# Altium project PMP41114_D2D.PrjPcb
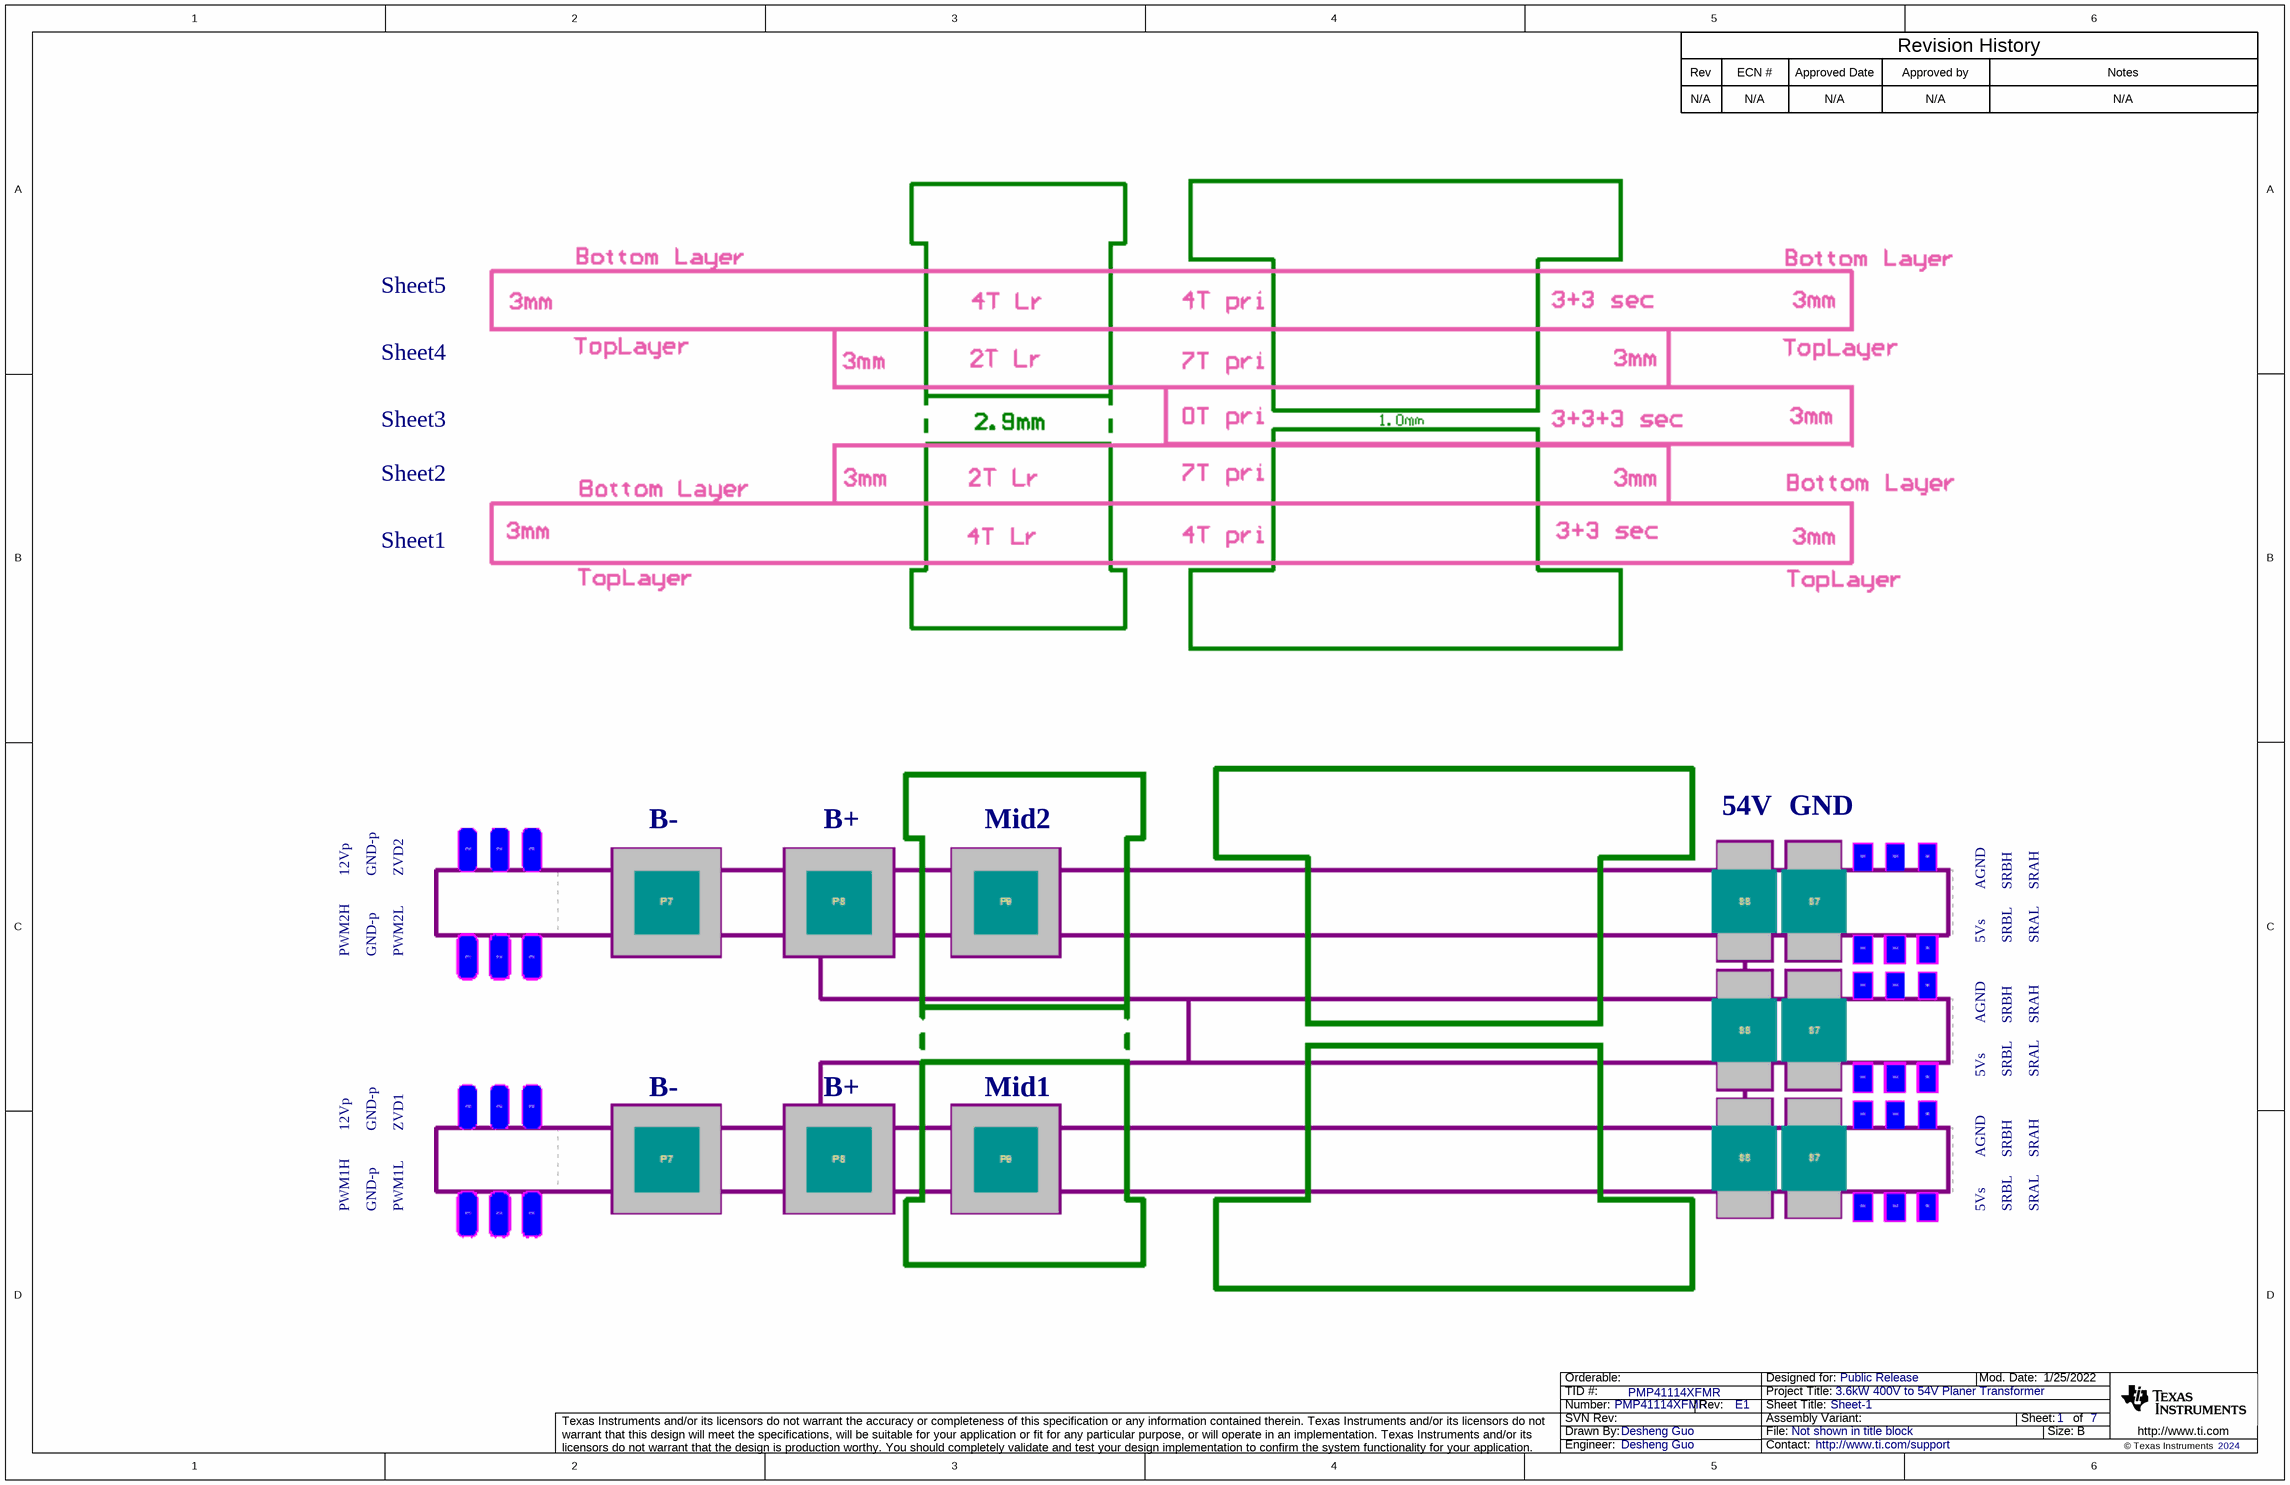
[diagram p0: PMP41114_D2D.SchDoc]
CopyrightYear: 2024; PCB_Layout: Desheng Guo; PCB_Rev: E1; PRJ_Customer: Public Release; PRJ_Engineer: Desheng Guo; PRJ_Number: PMP41114XFMR; PRJ_Title: 3.6kW 400V to 54V Planer Transformer; SCH_Rev: E1; TechSupport: http://www.ti.com/support; TID: PMP41114XFMR
7 sheets, 148 parts. Net scope: flat (ports and power ports of the same name join across sheets).
Board file: PMP41114_XFMR.PcbDoc
Sheets:
  PMP41114_D2D.SchDoc
  PMP41114_D2D_Sheet1.SchDoc
  PMP41114_D2D_Sheet2.SchDoc
  PMP41114_D2D_Sheet3.SchDoc
  PMP41114_D2D_Sheet5.SchDoc
  PMP41114_D2D_Sheet4.SchDoc
  PMP41114_D2D_Hardware.SchDoc

## Sheet PMP41114_D2D.SchDoc: Sheet-1
size 431 x 279 mm; Date: Not shown in title block; ApprovedBy: Not shown in title block; CheckedBy: Not shown in title block; Author: Not shown in title block; CompanyName: Not shown in title block; DrawnBy: Desheng Guo; Engineer: Not shown in title block; Organization: Not shown in title block; Address1: Not shown in title block; Address2: Not shown in title block; Address3: Not shown in title block; Address4: Not shown in title block; DocumentNumber: 1; Revision: Use project parameter SCH_Rev; SheetNumber: 1; SheetTotal: 7; PageSetup: Record=PageOptions¦CenterHorizontal=True¦CenterVertical=True¦PrintScale=1.00¦XCorrection=1.00¦YCorrection=1.00¦PrintKind=0¦BorderSize=5000000¦LeftOffset=0¦BottomOffset=0¦Orientation=2¦PaperLength=1000¦PaperWidth=1000¦Scale=100¦PaperSource=15¦PrintQuality=600¦MediaType=1¦DitherType=10¦PaperKind=Letter¦PrintScaleMode=1

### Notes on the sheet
- Rev
- N/A
- ECN #
- Approved Date
- Approved by
- Revision History
- Notes
- Sheet5
- Sheet4
- Sheet3
- Sheet2
- Sheet1
- B-
- B+
- Mid2
- 54V
- GND
- 12Vp
- GND-p
- ZVD2
- AGND
- SRBH
- SRAH
- PWM2H
- PWM2L
- 5Vs
- SRBL
- SRAL
- Mid1
- ZVD1
- PWM1H
- PWM1L

## Sheet PMP41114_D2D_Sheet1.SchDoc
size 431 x 279 mm; Date: Not shown in title block; ApprovedBy: Not shown in title block; CheckedBy: Not shown in title block; Author: Not shown in title block; CompanyName: Not shown in title block; Engineer: Not shown in title block; Organization: Not shown in title block; Address1: Not shown in title block; Address2: Not shown in title block; Address3: Not shown in title block; Address4: Not shown in title block; DocumentNumber: 2; Revision: Use project parameter SCH_Rev; SheetNumber: 2; SheetTotal: 7; PageSetup: Record=PageOptions¦CenterHorizontal=True¦CenterVertical=True¦PrintScale=1.00¦XCorrection=1.00¦YCorrection=1.00¦PrintKind=0¦BorderSize=5000000¦LeftOffset=0¦BottomOffset=0¦Orientation=2¦PaperLength=1000¦PaperWidth=1000¦Scale=100¦PaperSource=15¦PrintQuality=600¦MediaType=1¦DitherType=10¦PaperKind=Letter¦PrintScaleMode=1
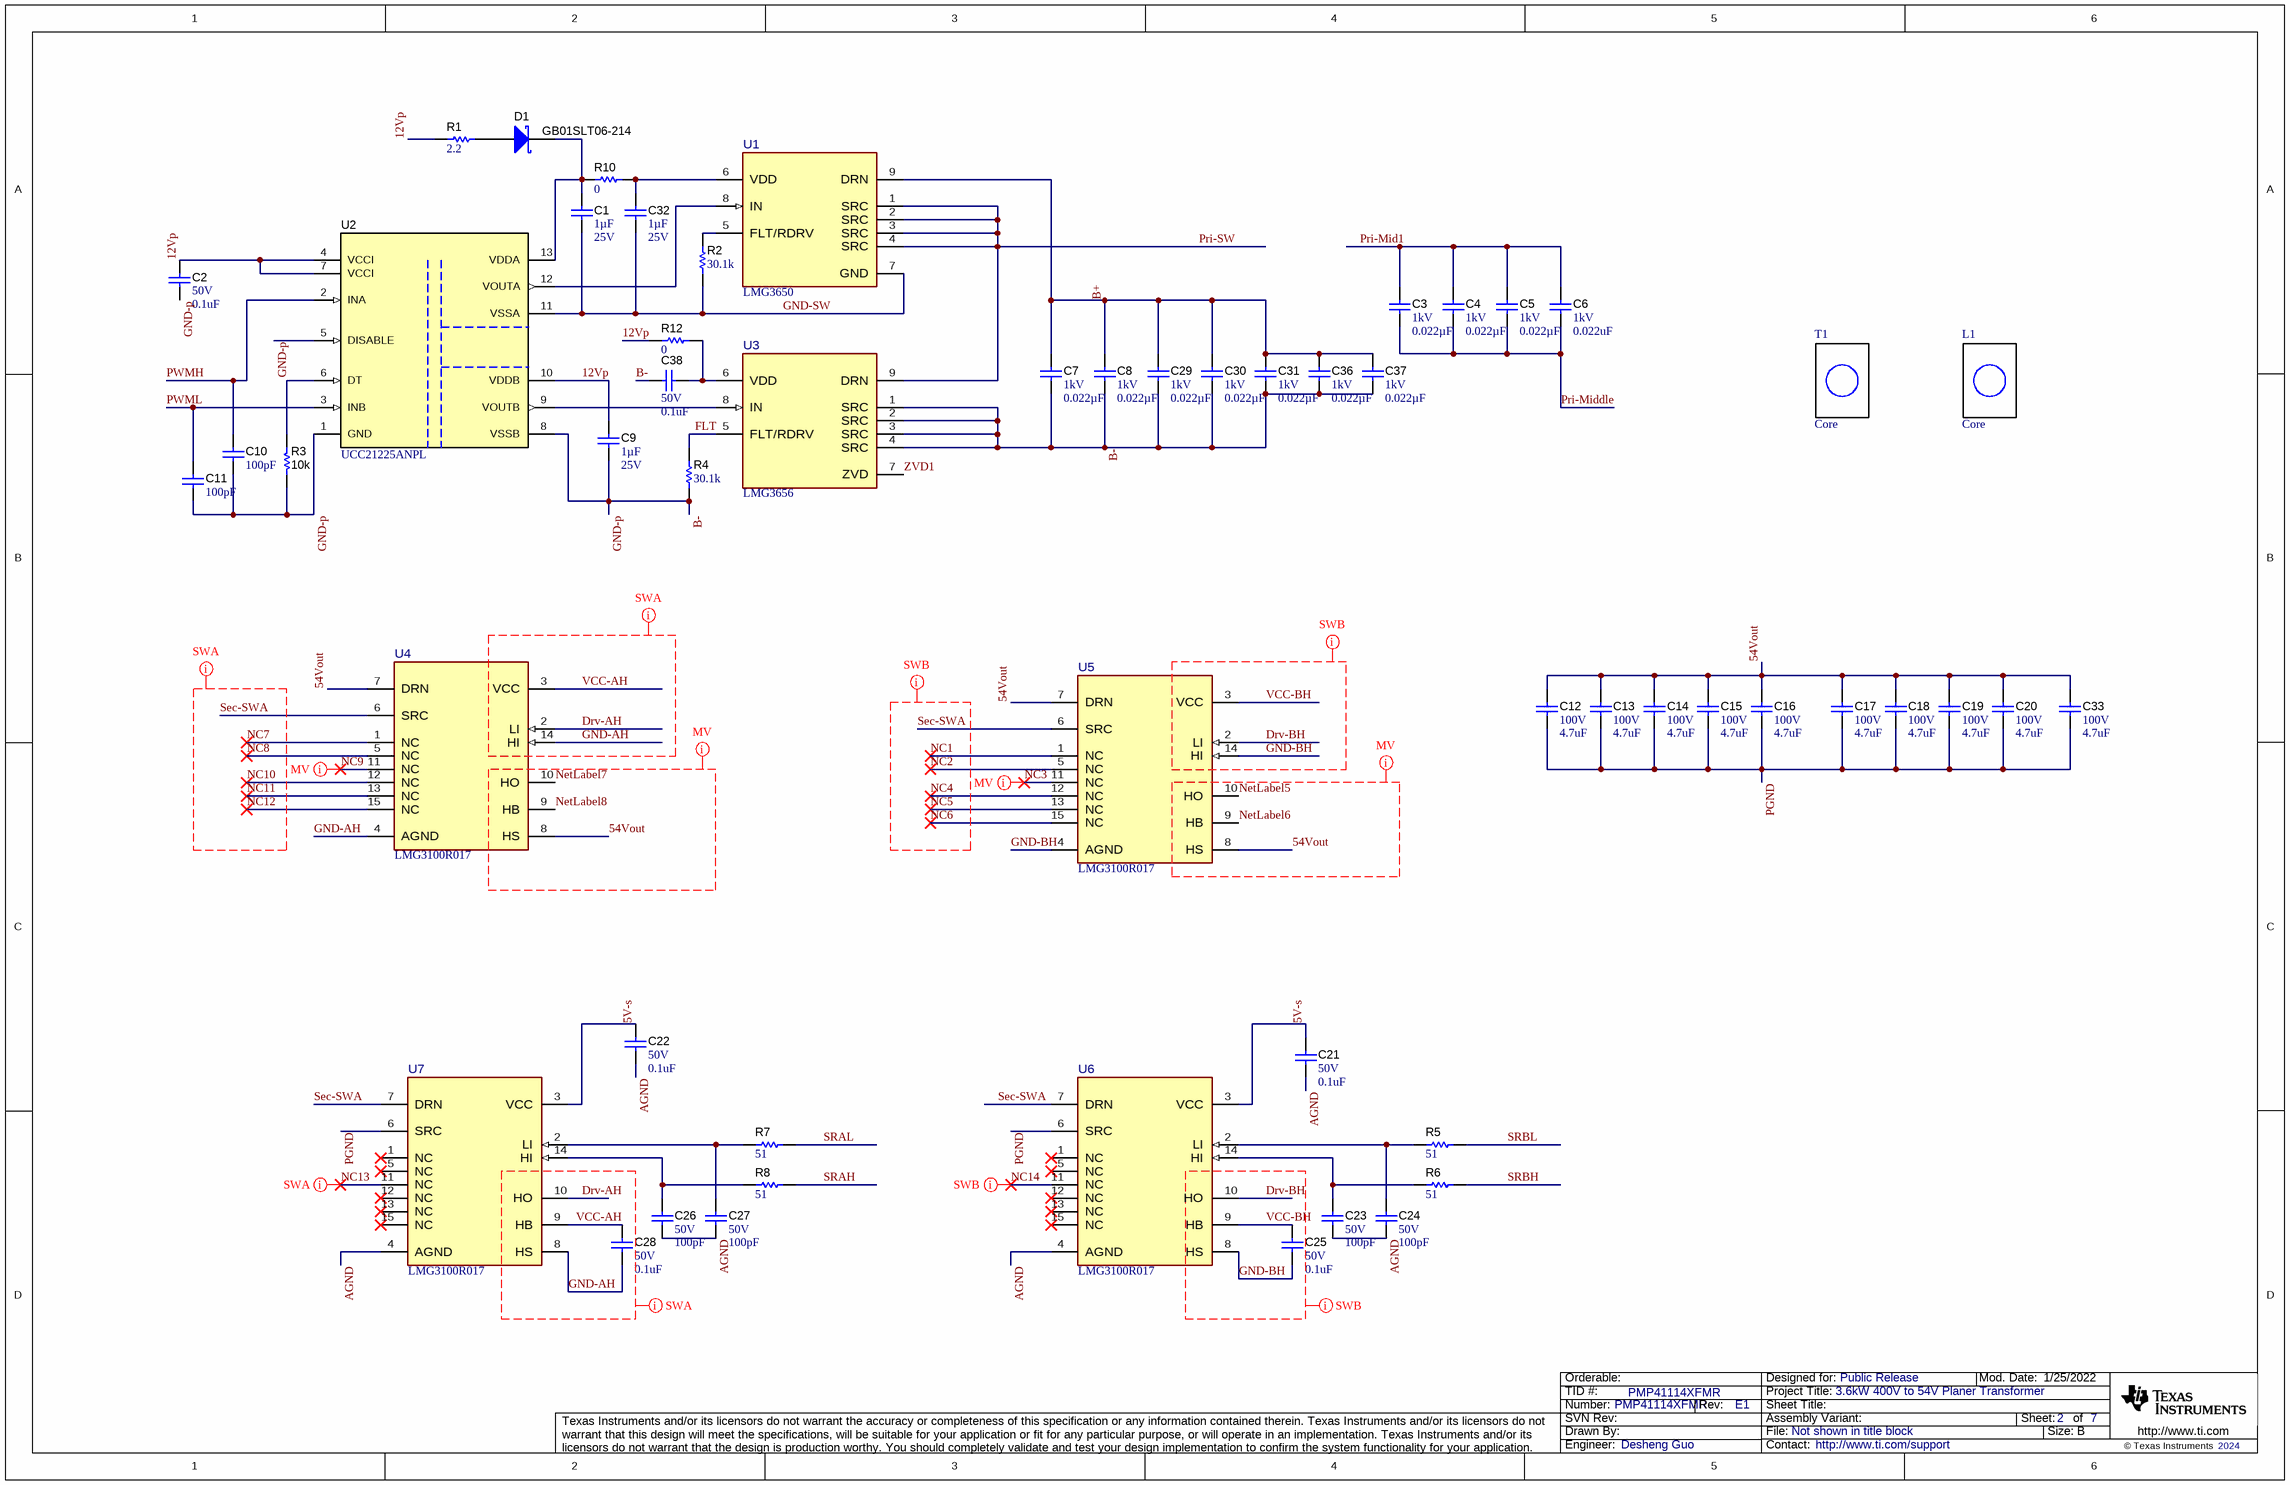
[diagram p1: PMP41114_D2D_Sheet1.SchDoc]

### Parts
C1  Cap_F: 1µF  VDC_V: 25V  [0603]  (hidden comment: CGJ3E1X7R1E105K080AC)
C2  VDC_V: 50V  ValueDisplayed: 0.1uF  [0402]  (hidden comment: C1005X7R1H104K050BB)
C3  VDC_V: 1kV  ValueDisplayed: 0.022µF  [1206_190]  (hidden comment: C1206C223KDRACTU)
C4  VDC_V: 1kV  ValueDisplayed: 0.022µF  [1206_190]  (hidden comment: C1206C223KDRACTU)
C5  VDC_V: 1kV  ValueDisplayed: 0.022µF  [1206_190]  (hidden comment: C1206C223KDRACTU)
C6  VDC_V: 1kV  ValueDisplayed: 0.022uF  [1206_190]  (hidden comment: C1206C223KDRACTU)
C7  VDC_V: 1kV  ValueDisplayed: 0.022µF  [1206_190]  (hidden comment: C1206C223KDRACTU)
C8  VDC_V: 1kV  ValueDisplayed: 0.022µF  [1206_190]  (hidden comment: C1206C223KDRACTU)
C9  Cap_F: 1µF  VDC_V: 25V  [0603]  (hidden comment: CGJ3E1X7R1E105K080AC)
C10  ValueDisplayed: 100pF  [0402]  (hidden comment: 885012205055)
C11  ValueDisplayed: 100pF  [0402]  (hidden comment: 885012205055)
C12  VDC_V: 100V  ValueDisplayed: 4.7uF  [1206_180]  (hidden comment: GRM31CZ72A475KE11L)
C13  VDC_V: 100V  ValueDisplayed: 4.7uF  [1206_180]  (hidden comment: GRM31CZ72A475KE11L)
C14  VDC_V: 100V  ValueDisplayed: 4.7uF  [1206_180]  (hidden comment: GRM31CZ72A475KE11L)
C15  VDC_V: 100V  ValueDisplayed: 4.7uF  [1206_180]  (hidden comment: GRM31CZ72A475KE11L)
C16  VDC_V: 100V  ValueDisplayed: 4.7uF  [1206_180]  (hidden comment: GRM31CZ72A475KE11L)
C17  VDC_V: 100V  ValueDisplayed: 4.7uF  [1206_180]  (hidden comment: GRM31CZ72A475KE11L)
C18  VDC_V: 100V  ValueDisplayed: 4.7uF  [1206_180]  (hidden comment: GRM31CZ72A475KE11L)
C19  VDC_V: 100V  ValueDisplayed: 4.7uF  [1206_180]  (hidden comment: GRM31CZ72A475KE11L)
C20  VDC_V: 100V  ValueDisplayed: 4.7uF  [1206_180]  (hidden comment: GRM31CZ72A475KE11L)
C21  VDC_V: 50V  ValueDisplayed: 0.1uF  [0402]  (hidden comment: GRM155R71H104ME14D)
C22  VDC_V: 50V  ValueDisplayed: 0.1uF  [0402]  (hidden comment: GRM155R71H104ME14D)
C23  VDC_V: 50V  ValueDisplayed: 100pF  [0402]  (hidden comment: CC0402KRX7R9BB101)
C24  VDC_V: 50V  ValueDisplayed: 100pF  [0402]  (hidden comment: CC0402KRX7R9BB101)
C25  VDC_V: 50V  ValueDisplayed: 0.1uF  [0402]  (hidden comment: C1005X7R1H104K050BE)
C26  VDC_V: 50V  ValueDisplayed: 100pF  [0402]  (hidden comment: CC0402KRX7R9BB101)
C27  VDC_V: 50V  ValueDisplayed: 100pF  [0402]  (hidden comment: CC0402KRX7R9BB101)
C28  VDC_V: 50V  ValueDisplayed: 0.1uF  [0402]  (hidden comment: C1005X7R1H104K050BE)
C29  VDC_V: 1kV  ValueDisplayed: 0.022µF  [1206_190]  (hidden comment: C1206C223KDRACTU)
C30  VDC_V: 1kV  ValueDisplayed: 0.022µF  [1206_190]  (hidden comment: C1206C223KDRACTU)
C31  VDC_V: 1kV  ValueDisplayed: 0.022µF  [1206_190]  (hidden comment: C1206C223KDRACTU)
C32  Cap_F: 1µF  VDC_V: 25V  [0603]  (hidden comment: CGJ3E1X7R1E105K080AC)
C33  VDC_V: 100V  ValueDisplayed: 4.7uF  [1206_180]  (hidden comment: GRM31CZ72A475KE11L)
C36  VDC_V: 1kV  ValueDisplayed: 0.022µF  [1206_190]  (hidden comment: C1206C223KDRACTU)
C37  VDC_V: 1kV  ValueDisplayed: 0.022µF  [1206_190]  (hidden comment: C1206C223KDRACTU)
C38  VDC_V: 50V  ValueDisplayed: 0.1uF  [0402]  (hidden comment: C1005X7R1H104K050BB)
D1  GB01SLT06-214  [SMB]
L1  Core  [ER25/10/11]  (no BOM)
R1  ValueDisplayed: 2.2  [0805_HV]  (hidden comment: RC0805JR-072R2L)
R2  ValueDisplayed: 30.1k  [0402]  (hidden comment: CRCW040230K1FKED)
R3  ValueDisplayed: 10k  [0402]  (hidden comment: CRCW040210K0JNED)
R4  ValueDisplayed: 30.1k  [0402]  (hidden comment: CRCW040230K1FKED)
R5  ValueDisplayed: 51  [0402]  (hidden comment: RC0402JR-0751RL)
R6  ValueDisplayed: 51  [0402]  (hidden comment: RC0402JR-0751RL)
R7  ValueDisplayed: 51  [0402]  (hidden comment: RC0402JR-0751RL)
R8  ValueDisplayed: 51  [0402]  (hidden comment: RC0402JR-0751RL)
R10  ValueDisplayed: 0  [0402]  (hidden comment: RC0402JR-070RL)
R12  ValueDisplayed: 0  [0402]  (hidden comment: RC0402JR-070RL)
T1  Core  [PQ32]  (no BOM)
U1  PartNumber: LMG3650  [KLA0009A-MFG]  (hidden comment: LMG365x)
U2  UCC21225ANPL  [NPL0013A]
U3  PartNumber: LMG3656  [KLA0009A-MFG]  (hidden comment: LMG365x)
U4  LMG3100R017  [VBE0015A-MFG]
U5  LMG3100R017  [VBE0015A-MFG]
U6  LMG3100R017  [VBE0015A-MFG]
U7  LMG3100R017  [VBE0015A-MFG]

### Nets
5V-s: C21.1 C22.1 U6.3(VCC) U7.3(VCC)  [project net 5V-s_2]
12Vp: C2.1 C9.1 R1.1 R12.1 U2.4(VCCI) U2.7(VCCI) U2.10(VDDB)  [project net 12Vp_2]
54Vout: C12.1 C13.1 C14.1 C15.1 C16.1 C17.1 C18.1 C19.1 C20.1 C33.1 U4.7(DRN) U4.8(HS) U5.7(DRN) U5.8(HS)  [project net 54Vout_2]
AGND: C21.2 C22.2 C23.2 C24.2 C26.2 C27.2 U6.4(AGND) U7.4(AGND)  [project net AGND_2]
B+: C7.1 C8.1 C29.1 C30.1 C31.1 C36.1 C37.1 U1.9(DRN)  [project net B+_2]
B-: C2.2 C7.2 C8.2 C9.2 C10.2 C11.2 C29.2 C30.2 C31.2 C36.2 C37.2 C38.1 R3.1 R4.1 U2.1(GND) U2.5(DISABLE) U2.8(VSSB) U3.1(SRC) U3.2(SRC) U3.3(SRC) U3.4(SRC)  [also labelled GND-p]  [project net B-_2]
Drv-AH: U4.2(LI) U7.10(HO)  [project net Drv-AH_2]
Drv-BH: U5.2(LI) U6.10(HO)  [project net Drv-BH_2]
FLT: R4.2 U3.5(FLT/RDRV)  [project net FLT_2]
GND-AH: C28.2 U4.4(AGND) U4.14(HI) U7.8(HS)  [project net GND-AH_2]
GND-BH: C25.2 U5.4(AGND) U5.14(HI) U6.8(HS)  [project net GND-BH_2]
GND-SW: C1.2 C32.2 R2.1 U1.7(GND) U2.11(VSSA)  [project net GND-SW_2]
NC1: U5.1(NC)  [project net NC1_2]
NC2: U5.5(NC)  [project net NC2_2]
NC3: U5.11(NC)  [project net NC3_2]
NC4: U5.12(NC)  [project net NC4_2]
NC5: U5.13(NC)  [project net NC5_2]
NC6: U5.15(NC)  [project net NC6_2]
NC7: U4.1(NC)  [project net NC7_2]
NC8: U4.5(NC)  [project net NC8_2]
NC9: U4.11(NC)  [project net NC9_2]
NC10: U4.12(NC)  [project net NC10_2]
NC11: U4.13(NC)  [project net NC11_2]
NC12: U4.15(NC)  [project net NC12_2]
NC13: U7.11(NC)  [project net NC13_2]
NC14: U6.11(NC)  [project net NC14_2]
NetLabel5: U5.10(HO)  [project net NetLabel5_2]
NetLabel6: U5.9(HB)  [project net NetLabel6_2]
NetLabel7: U4.10(HO)  [project net NetLabel7_2]
NetLabel8: U4.9(HB)  [project net NetLabel8_2]
PGND: C12.2 C13.2 C14.2 C15.2 C16.2 C17.2 C18.2 C19.2 C20.2 C33.2 U6.6(SRC) U7.6(SRC)  [project net PGND_2]
Pri-Mid1: C3.1 C4.1 C5.1 C6.1  [project net Pri-Mid1_2]
Pri-Middle: C3.2 C4.2 C5.2 C6.2  [project net Pri-Middle_2]
Pri-SW: U1.1(SRC) U1.2(SRC) U1.3(SRC) U1.4(SRC) U3.9(DRN)  [project net Pri-SW_2]
PWMH: C10.1 U2.2(INA)  [project net PWMH_2]
PWML: C11.1 U2.3(INB)  [project net PWML_2]
Sec-SWA: U4.6(SRC) U5.6(SRC) U6.7(DRN) U7.7(DRN)  [project net Sec-SWA_2]
SRAH: R8.2  [project net SRAH_2]
SRAL: R7.2  [project net SRAL_2]
SRBH: R6.2  [project net SRBH_2]
SRBL: R5.2  [project net SRBL_2]
VCC-AH: C28.1 U4.3(VCC) U7.9(HB)  [project net VCC-AH_2]
VCC-BH: C25.1 U5.3(VCC) U6.9(HB)  [project net VCC-BH_2]
ZVD1: U3.7(ZVD)  [project net ZVD1_2]
NetC1_1: C1.1 D1.1(K) R10.1 U2.13(VDDA)
NetC23_1: C23.1 R6.1 U6.14(HI)
NetC24_1: C24.1 R5.1 U6.2(LI)
NetC26_1: C26.1 R8.1 U7.14(HI)
NetC27_1: C27.1 R7.1 U7.2(LI)
NetC32_1: C32.1 R10.2 U1.6(VDD)
NetC38_2: C38.2 R12.2 U3.6(VDD)
NetD1_2: D1.2(A) R1.2
NetR2_2: R2.2 U1.5(FLT/RDRV)
NetR3_2: R3.2 U2.6(DT)
NetU1_8: U1.8(IN) U2.12(VOUTA)
NetU2_9: U2.9(VOUTB) U3.8(IN)

Not connected (* = marked no-connect by the designer): U6 1(NC)* 5(NC)* 12(NC)* 13(NC)* 15(NC)*; U7 1(NC)* 5(NC)* 12(NC)* 13(NC)* 15(NC)*

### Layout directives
net class SWA: Drv-AH, GND-AH, NC7, NC8, NC10, NC11, NC12, NC13_2, Sec-SWA, VCC-AH
net class SWB: Drv-BH, GND-BH, NC1, NC2, NC4, NC5, NC6, NC14_2, Sec-SWA, VCC-BH
net class MV: 54Vout, NC3_2, NC9_2, NetLabel5, NetLabel6, NetLabel7, NetLabel8

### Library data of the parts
C1 C9 C32 = CMP-0083856-1: CAP, CERM, 1 µF, 25 V,+/- 10%, X7R, 0603; Manufacturer: TDK; TaMin_C: -55°C; Polarized: N; SizeAreaWB_mm2: 4.68; U/M: EA; Value: 1uF; TaMax_C: 125°C; SizeZ_mm: 1; SizeX_mm: 1.6; SizeY_mm: 0.8; SizeArea_mm2: 1.28; AEC Category: Q200
C2 C38 = CMP-0006297-2: CAP, CERM, 0.1 uF, 50 V, +/- 10%, X7R, 0402; Manufacturer: TDK; TaMin_C: -55°C; ESR_ohm: 0.039064; Polarized: N; SizeAreaWB_mm2: 3; Value1: 0.039064 ohm; U/M: EA; Value: 0.1uF; TaMax_C: 125°C; SizeZ_mm: 0.6; SizeX_mm: 1; SizeY_mm: 0.5; Cap_F: 100nF; IRMS_A: 8.14669dA; AEC Category: Q200
C3-C8 C29-C31 C36 C37 = CMP-0084048-1: CAP, CERM, 0.022 µF, 1000 V,+/- 10%, X7R, AEC-Q200 Grade 1, 1206; Manufacturer: Kemet; TaMin_C: -55°C; Polarized: N; SizeAreaWB_mm2: 10.92; U/M: EA; Value: 0.022uF; TaMax_C: 125°C; SizeZ_mm: 1.9; SizeX_mm: 3.2; SizeY_mm: 1.6; Cap_Case: 1206; Value2: 1000V; SizeArea_mm2: 5.12; AEC Qualified: Y; Cap_F: 22nF; AEC Grade: 1; AEC Category: Q200
C10 C11 = CMP-0006230-2: CAP, CERM, 100 pF, 50 V, +/- 10%, X7R, 0402; Manufacturer: Wurth Elektronik; Polarized: N; Value: 100pF; U/M: EA; Value1: Unknown; VDC_V: 50V; TaMin_C: -55°C; TaMax_C: 125°C; AEC Category: Q200; SizeArea_mm2: 0.5; SizeAreaWB_mm2: 3; SizeX_mm: 1; SizeZ_mm: 0.6
C12-C20 C33 = CMP-0008802-2: CAP, CERM, 4.7 uF, 100 V, +/- 10%, X7R, 1206; Manufacturer: Samsung; TaMin_C: -55°C; Polarized: N; SizeAreaWB_mm2: 10.92; Value1: Unknown; U/M: EA; Value: 4.7uF; TaMax_C: 125°C; SizeZ_mm: 1.8; SizeX_mm: 3.2; SizeY_mm: 1.6; Cap_Case: 1206; SizeArea_mm2: 5.12; Cap_F: 4.7µF; AEC Category: Q200
C21 C22 = CMP-0006675-2: CAP, CERM, 0.1 uF, 50 V, +/- 20%, X7R, 0402; Manufacturer: MuRata; TaMin_C: -55°C; Polarized: N; SizeAreaWB_mm2: 3; Value1: Unknown; U/M: EA; Value: 0.1uF; TaMax_C: 125°C; SizeZ_mm: 0.6; SizeX_mm: 1; SizeY_mm: 0.5; Cap_F: 100nF; AEC Category: Q200
C23 C24 C26 C27 = CMP-0006305-2: CAP, CERM, 100 pF, 50 V, +/- 10%, X7R, 0402; Manufacturer: Yageo America; TaMin_C: -55°C; Polarized: N; SizeAreaWB_mm2: 3; Value1: Unknown; U/M: EA; Value: 100pF; TaMax_C: 125°C; SizeZ_mm: 0.6; SizeX_mm: 1; SizeY_mm: 0.5; AEC Category: Q200
C25 C28 = CMP-0064946-2: CAP, CERM, 0.1 uF, 50 V,+/- 10%, X7R, 0402; Manufacturer: TDK; TaMin_C: -55°C; Polarized: N; SizeAreaWB_mm2: 3; Value1: Unknown; U/M: EA; Value: 0.1uF; TaMax_C: 125°C; SizeZ_mm: 0.6; SizeX_mm: 1; SizeY_mm: 0.5; Cap_F: 100nF; AEC Category: Q200
D1 = CMP-0076998-2: Diode, Schottky, 650 V, 1 A, SMB; Manufacturer: GeneSiC Semiconductor; Value1: 1A; SizeZ_mm: 2.6; Value: 650V; SizeAreaWB_mm2: 44.156; TJmax_C: 175°C; RJC_CperW: 3.55; SizeArea_mm2: 21.336; AEC Category: Q101; Value2: 2V; SizeY_mm: 3.81; SizeX_mm: 5.6
L1 T1 = CorePlace
R1 = CMP-0020812-2: RES, 2.2, 5%, 0.125 W, 0805; Manufacturer: Yageo America; Power_W: 125mW; TempCo: 200 ppm/C; Value_Code: 2R20; U/M: EA; Value: 2.2; EIA_Code: E24; SizeX_mm: 2; SizeY_mm: 1.25; SizeZ_mm: 1.45; Value2: 0.125W; SizeArea_mm2: 2.5; VDC_V: 150V; AEC Category: Q200
R2 R4 = CMP-0026284-2: RES, 30.1 k, 1%, 0.063 W, AEC-Q200 Grade 0, 0402; Manufacturer: Vishay-Dale; Power_W: 63mW; TempCo: 100 ppm/C; Value_Code: 30k1; Value: 30.1k; EIA_Code: E96; SizeX_mm: 1; SizeY_mm: 0.5; SizeZ_mm: 0.6; Value2: 0.063W; AEC Qualified: Y; VDC_V: 50V; AEC Category: Q200; AEC Grade: 0
R3 = CMP-0026825-5: RES, 10 k, 5%, 0.063 W, AEC-Q200 Grade 0, 0402; Manufacturer: Vishay-Dale; Value: 10k; Value_Code: 10k0; Power_W: 63mW; Value2: 0.063W; VDC_V: 50V; TempCo: 200 ppm/C; EIA_Code: E24; AEC Category: Q200; AEC Qualified: Y; AEC Grade: 0; SizeArea_mm2: 0.5; SizeX_mm: 1; SizeZ_mm: 0.6
R5-R8 = CMP-0027006-2: RES, 51, 5%, 0.0625 W, 0402; Manufacturer: Yageo America; Power_W: 62.5mW; TempCo: 100 ppm/C; Value_Code: 51R0; U/M: EA; Value: 51; EIA_Code: E24; SizeX_mm: 1; SizeY_mm: 0.5; SizeZ_mm: 0.6; AEC Qualified: N; VDC_V: 50V; AEC Category: Q200
R10 R12 = CMP-0027004-2: RES, 0, 5%, 0.063 W, 0402; Manufacturer: Yageo America; Power_W: 63mW; TempCo: 200 ppm/C; Value_Code: 0000; U/M: EA; Value: 0; EIA_Code: E24; SizeX_mm: 1; SizeY_mm: 0.5; SizeZ_mm: 0.6; Value2: 0.063W; VDC_V: 50V; AEC Category: Q200
U1 U3 = CMP-0120607-2: Manufacturer: Texas Instruments; SizeZ_mm: 2.35mm; AEC Qualified: No; Standoff Height: 0.1mm; AEC Category: Q200; CompType: IC
U2 = CMP-0013548-2: 4A/6A Isolated Dual-Channel Gate Driver, NPL0013A (VLGA-13); Manufacturer: Texas Instruments; SizeX_mm: 5; CompType: IC; SizeZ_mm: 1; SizeArea_mm2: 25; SizeAreaWB_mm2: 49; U/M: EA
U4-U7 = CMP-0043784-1: 100-V, 64-A GaN with Integrated Driver; Manufacturer: Texas Instruments; SizeZ_mm: 0.85mm; AEC Qualified: No; Max Supply Voltage: 5.25V; Min Supply Voltage: 4.75V; Nominal Supply Current: 3mA; Number Of Drivers: 1; Propagation Delay: 55ns; Standoff Height: 0mm; TJmax_C: +125°C

## Sheet PMP41114_D2D_Sheet2.SchDoc
size 431 x 279 mm; Date: Not shown in title block; ApprovedBy: Not shown in title block; CheckedBy: Not shown in title block; Author: Not shown in title block; CompanyName: Not shown in title block; Engineer: Not shown in title block; Organization: Not shown in title block; Address1: Not shown in title block; Address2: Not shown in title block; Address3: Not shown in title block; Address4: Not shown in title block; DocumentNumber: 2; Revision: Use project parameter SCH_Rev; SheetNumber: 3; SheetTotal: 7; PageSetup: Record=PageOptions¦CenterHorizontal=True¦CenterVertical=True¦PrintScale=1.00¦XCorrection=1.00¦YCorrection=1.00¦PrintKind=0¦BorderSize=5000000¦LeftOffset=0¦BottomOffset=0¦Orientation=2¦PaperLength=1000¦PaperWidth=1000¦Scale=100¦PaperSource=15¦PrintQuality=600¦MediaType=1¦DitherType=10¦PaperKind=Letter¦PrintScaleMode=1
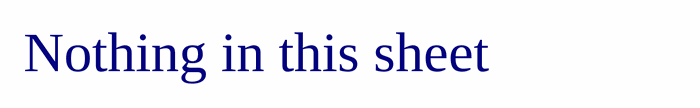
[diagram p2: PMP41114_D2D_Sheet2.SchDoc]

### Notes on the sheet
- Nothing in this sheet

## Sheet PMP41114_D2D_Sheet3.SchDoc
size 431 x 279 mm; Date: Not shown in title block; ApprovedBy: Not shown in title block; CheckedBy: Not shown in title block; Author: Not shown in title block; CompanyName: Not shown in title block; Engineer: Not shown in title block; Organization: Not shown in title block; Address1: Not shown in title block; Address2: Not shown in title block; Address3: Not shown in title block; Address4: Not shown in title block; DocumentNumber: 2; Revision: Use project parameter SCH_Rev; SheetNumber: 4; SheetTotal: 7; PageSetup: Record=PageOptions¦CenterHorizontal=True¦CenterVertical=True¦PrintScale=1.00¦XCorrection=1.00¦YCorrection=1.00¦PrintKind=0¦BorderSize=5000000¦LeftOffset=0¦BottomOffset=0¦Orientation=2¦PaperLength=1000¦PaperWidth=1000¦Scale=100¦PaperSource=15¦PrintQuality=600¦MediaType=1¦DitherType=10¦PaperKind=Letter¦PrintScaleMode=1
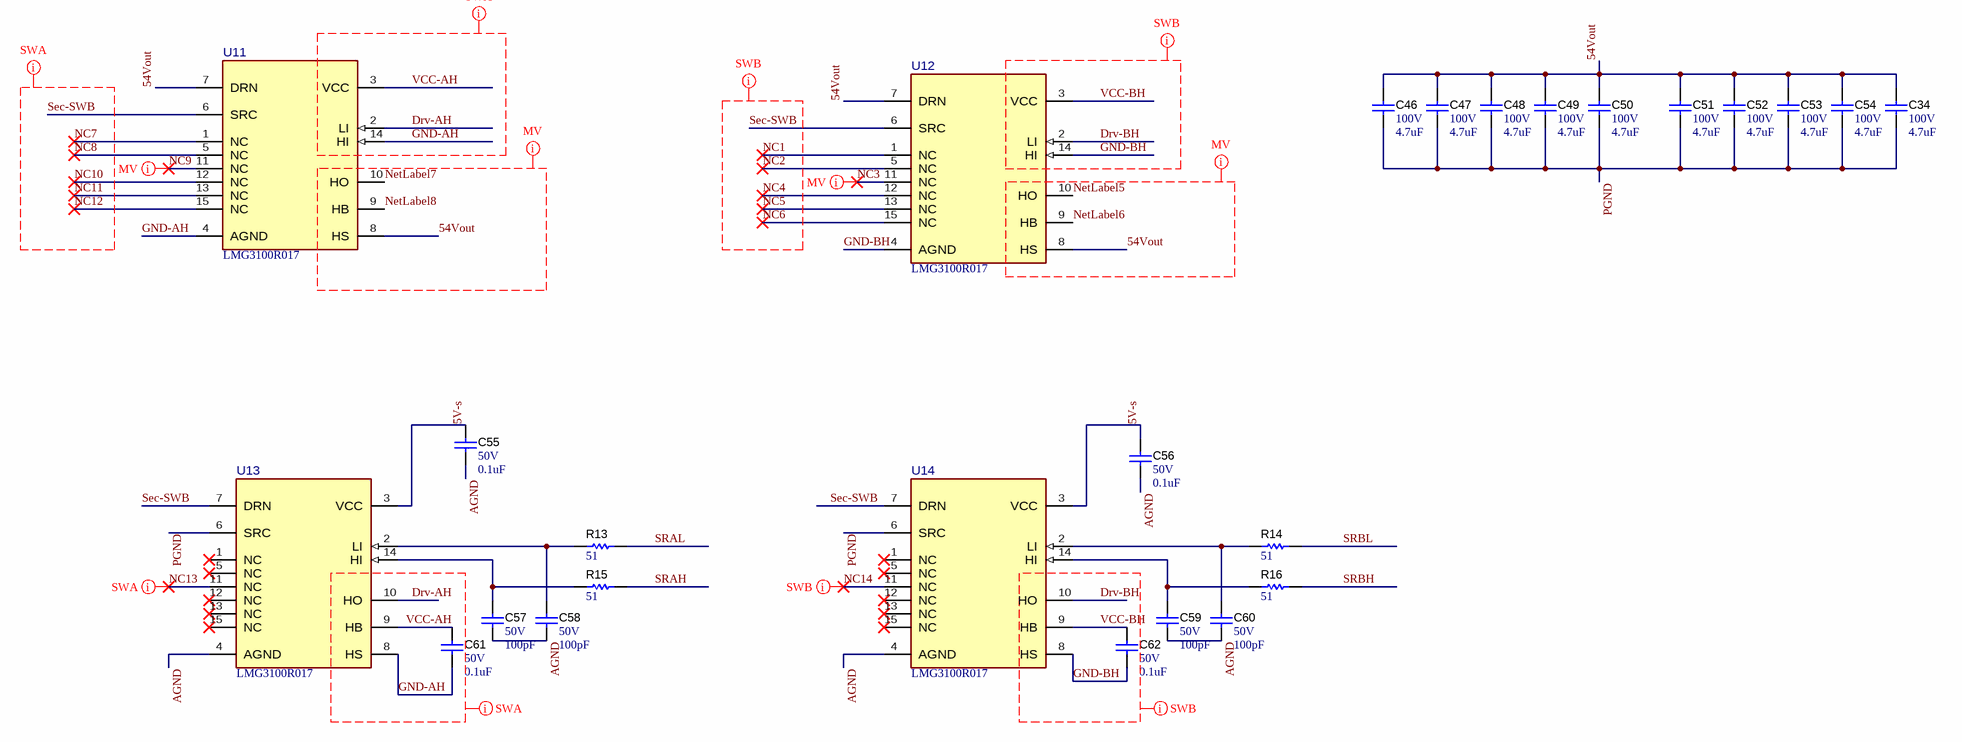
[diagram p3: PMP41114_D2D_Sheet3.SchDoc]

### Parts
C34  VDC_V: 100V  ValueDisplayed: 4.7uF  [1206_180]  (hidden comment: GRM31CZ72A475KE11L)
C46  VDC_V: 100V  ValueDisplayed: 4.7uF  [1206_180]  (hidden comment: GRM31CZ72A475KE11L)
C47  VDC_V: 100V  ValueDisplayed: 4.7uF  [1206_180]  (hidden comment: GRM31CZ72A475KE11L)
C48  VDC_V: 100V  ValueDisplayed: 4.7uF  [1206_180]  (hidden comment: GRM31CZ72A475KE11L)
C49  VDC_V: 100V  ValueDisplayed: 4.7uF  [1206_180]  (hidden comment: GRM31CZ72A475KE11L)
C50  VDC_V: 100V  ValueDisplayed: 4.7uF  [1206_180]  (hidden comment: GRM31CZ72A475KE11L)
C51  VDC_V: 100V  ValueDisplayed: 4.7uF  [1206_180]  (hidden comment: GRM31CZ72A475KE11L)
C52  VDC_V: 100V  ValueDisplayed: 4.7uF  [1206_180]  (hidden comment: GRM31CZ72A475KE11L)
C53  VDC_V: 100V  ValueDisplayed: 4.7uF  [1206_180]  (hidden comment: GRM31CZ72A475KE11L)
C54  VDC_V: 100V  ValueDisplayed: 4.7uF  [1206_180]  (hidden comment: GRM31CZ72A475KE11L)
C55  VDC_V: 50V  ValueDisplayed: 0.1uF  [0402]  (hidden comment: GRM155R71H104ME14D)
C56  VDC_V: 50V  ValueDisplayed: 0.1uF  [0402]  (hidden comment: GRM155R71H104ME14D)
C57  VDC_V: 50V  ValueDisplayed: 100pF  [0402]  (hidden comment: CC0402KRX7R9BB101)
C58  VDC_V: 50V  ValueDisplayed: 100pF  [0402]  (hidden comment: CC0402KRX7R9BB101)
C59  VDC_V: 50V  ValueDisplayed: 100pF  [0402]  (hidden comment: CC0402KRX7R9BB101)
C60  VDC_V: 50V  ValueDisplayed: 100pF  [0402]  (hidden comment: CC0402KRX7R9BB101)
C61  VDC_V: 50V  ValueDisplayed: 0.1uF  [0402]  (hidden comment: C1005X7R1H104K050BE)
C62  VDC_V: 50V  ValueDisplayed: 0.1uF  [0402]  (hidden comment: C1005X7R1H104K050BE)
R13  ValueDisplayed: 51  [0402]  (hidden comment: RC0402JR-0751RL)
R14  ValueDisplayed: 51  [0402]  (hidden comment: RC0402JR-0751RL)
R15  ValueDisplayed: 51  [0402]  (hidden comment: RC0402JR-0751RL)
R16  ValueDisplayed: 51  [0402]  (hidden comment: RC0402JR-0751RL)
U11  LMG3100R017  [VBE0015A-MFG]
U12  LMG3100R017  [VBE0015A-MFG]
U13  LMG3100R017  [VBE0015A-MFG]
U14  LMG3100R017  [VBE0015A-MFG]

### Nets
5V-s: C55.1 C56.1 U13.3(VCC) U14.3(VCC)  [project net 5V-s_4]
54Vout: C34.1 C46.1 C47.1 C48.1 C49.1 C50.1 C51.1 C52.1 C53.1 C54.1 U11.7(DRN) U11.8(HS) U12.7(DRN) U12.8(HS)  [project net 54Vout_4]
AGND: C55.2 C56.2 C57.2 C58.2 C59.2 C60.2 U13.4(AGND) U14.4(AGND)  [project net AGND_4]
Drv-AH: U11.2(LI) U13.10(HO)  [project net Drv-AH_4]
Drv-BH: U12.2(LI) U14.10(HO)  [project net Drv-BH_4]
GND-AH: C61.2 U11.4(AGND) U11.14(HI) U13.8(HS)  [project net GND-AH_4]
GND-BH: C62.2 U12.4(AGND) U12.14(HI) U14.8(HS)  [project net GND-BH_4]
NC1: U12.1(NC)  [project net NC1_4]
NC2: U12.5(NC)  [project net NC2_4]
NC3: U12.11(NC)  [project net NC3_4]
NC4: U12.12(NC)  [project net NC4_4]
NC5: U12.13(NC)  [project net NC5_4]
NC6: U12.15(NC)  [project net NC6_4]
NC7: U11.1(NC)  [project net NC7_4]
NC8: U11.5(NC)  [project net NC8_4]
NC9: U11.11(NC)  [project net NC9_4]
NC10: U11.12(NC)  [project net NC10_4]
NC11: U11.13(NC)  [project net NC11_4]
NC12: U11.15(NC)  [project net NC12_4]
NC13: U13.11(NC)  [project net NC13_4]
NC14: U14.11(NC)  [project net NC14_4]
NetLabel5: U12.10(HO)  [project net NetLabel5_4]
NetLabel6: U12.9(HB)  [project net NetLabel6_4]
NetLabel7: U11.10(HO)  [project net NetLabel7_4]
NetLabel8: U11.9(HB)  [project net NetLabel8_4]
PGND: C34.2 C46.2 C47.2 C48.2 C49.2 C50.2 C51.2 C52.2 C53.2 C54.2 U13.6(SRC) U14.6(SRC)  [project net PGND_4]
Sec-SWB: U11.6(SRC) U12.6(SRC) U13.7(DRN) U14.7(DRN)  [project net Sec-SWB_4]
SRAH: R15.2  [project net SRAH_4]
SRAL: R13.2  [project net SRAL_4]
SRBH: R16.2  [project net SRBH_4]
SRBL: R14.2  [project net SRBL_4]
VCC-AH: C61.1 U11.3(VCC) U13.9(HB)  [project net VCC-AH_4]
VCC-BH: C62.1 U12.3(VCC) U14.9(HB)  [project net VCC-BH_4]
NetC57_1: C57.1 R15.1 U13.14(HI)
NetC58_1: C58.1 R13.1 U13.2(LI)
NetC59_1: C59.1 R16.1 U14.14(HI)
NetC60_1: C60.1 R14.1 U14.2(LI)

Not connected (* = marked no-connect by the designer): U13 1(NC)* 5(NC)* 12(NC)* 13(NC)* 15(NC)*; U14 1(NC)* 5(NC)* 12(NC)* 13(NC)* 15(NC)*

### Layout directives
net class SWA: Drv-AH, GND-AH, NC7, NC8, NC10, NC11, NC12, NC13_4, Sec-SWB, VCC-AH
net class SWB: Drv-BH, GND-BH, NC1, NC2, NC4, NC5, NC6, NC14_4, Sec-SWB, VCC-BH
net class MV: 54Vout, NC3_4, NC9_4, NetLabel5, NetLabel6, NetLabel7, NetLabel8

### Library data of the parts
C34 C46-C54 = CMP-0008802-2: as C12 on sheet PMP41114_D2D_Sheet1
C55 C56 = CMP-0006675-2: as C21 on sheet PMP41114_D2D_Sheet1
C57-C60 = CMP-0006305-2: as C23 on sheet PMP41114_D2D_Sheet1
C61 C62 = CMP-0064946-2: as C25 on sheet PMP41114_D2D_Sheet1
R13-R16 = CMP-0027006-2: as R5 on sheet PMP41114_D2D_Sheet1
U11-U14 = CMP-0043784-1: as U4 on sheet PMP41114_D2D_Sheet1

## Sheet PMP41114_D2D_Sheet5.SchDoc
size A3; Date: Not shown in title block; ApprovedBy: Not shown in title block; CheckedBy: Not shown in title block; Author: Not shown in title block; CompanyName: Not shown in title block; Engineer: Not shown in title block; Organization: Not shown in title block; Address1: Not shown in title block; Address2: Not shown in title block; Address3: Not shown in title block; Address4: Not shown in title block; DocumentNumber: 1; Revision: Use project parameter SCH_Rev; SheetNumber: 5; SheetTotal: 7; PageSetup: Record=PageOptions¦CenterHorizontal=True¦CenterVertical=True¦PrintScale=0.69¦XCorrection=1.00¦YCorrection=1.00¦PrintKind=0¦BorderSize=5000000¦LeftOffset=0¦BottomOffset=0¦Orientation=2¦PaperLength=1000¦PaperWidth=1000¦Scale=100¦PaperSource=15¦PrintQuality=600¦MediaType=1¦DitherType=10¦PaperKind=Letter¦PrintScaleMode=1
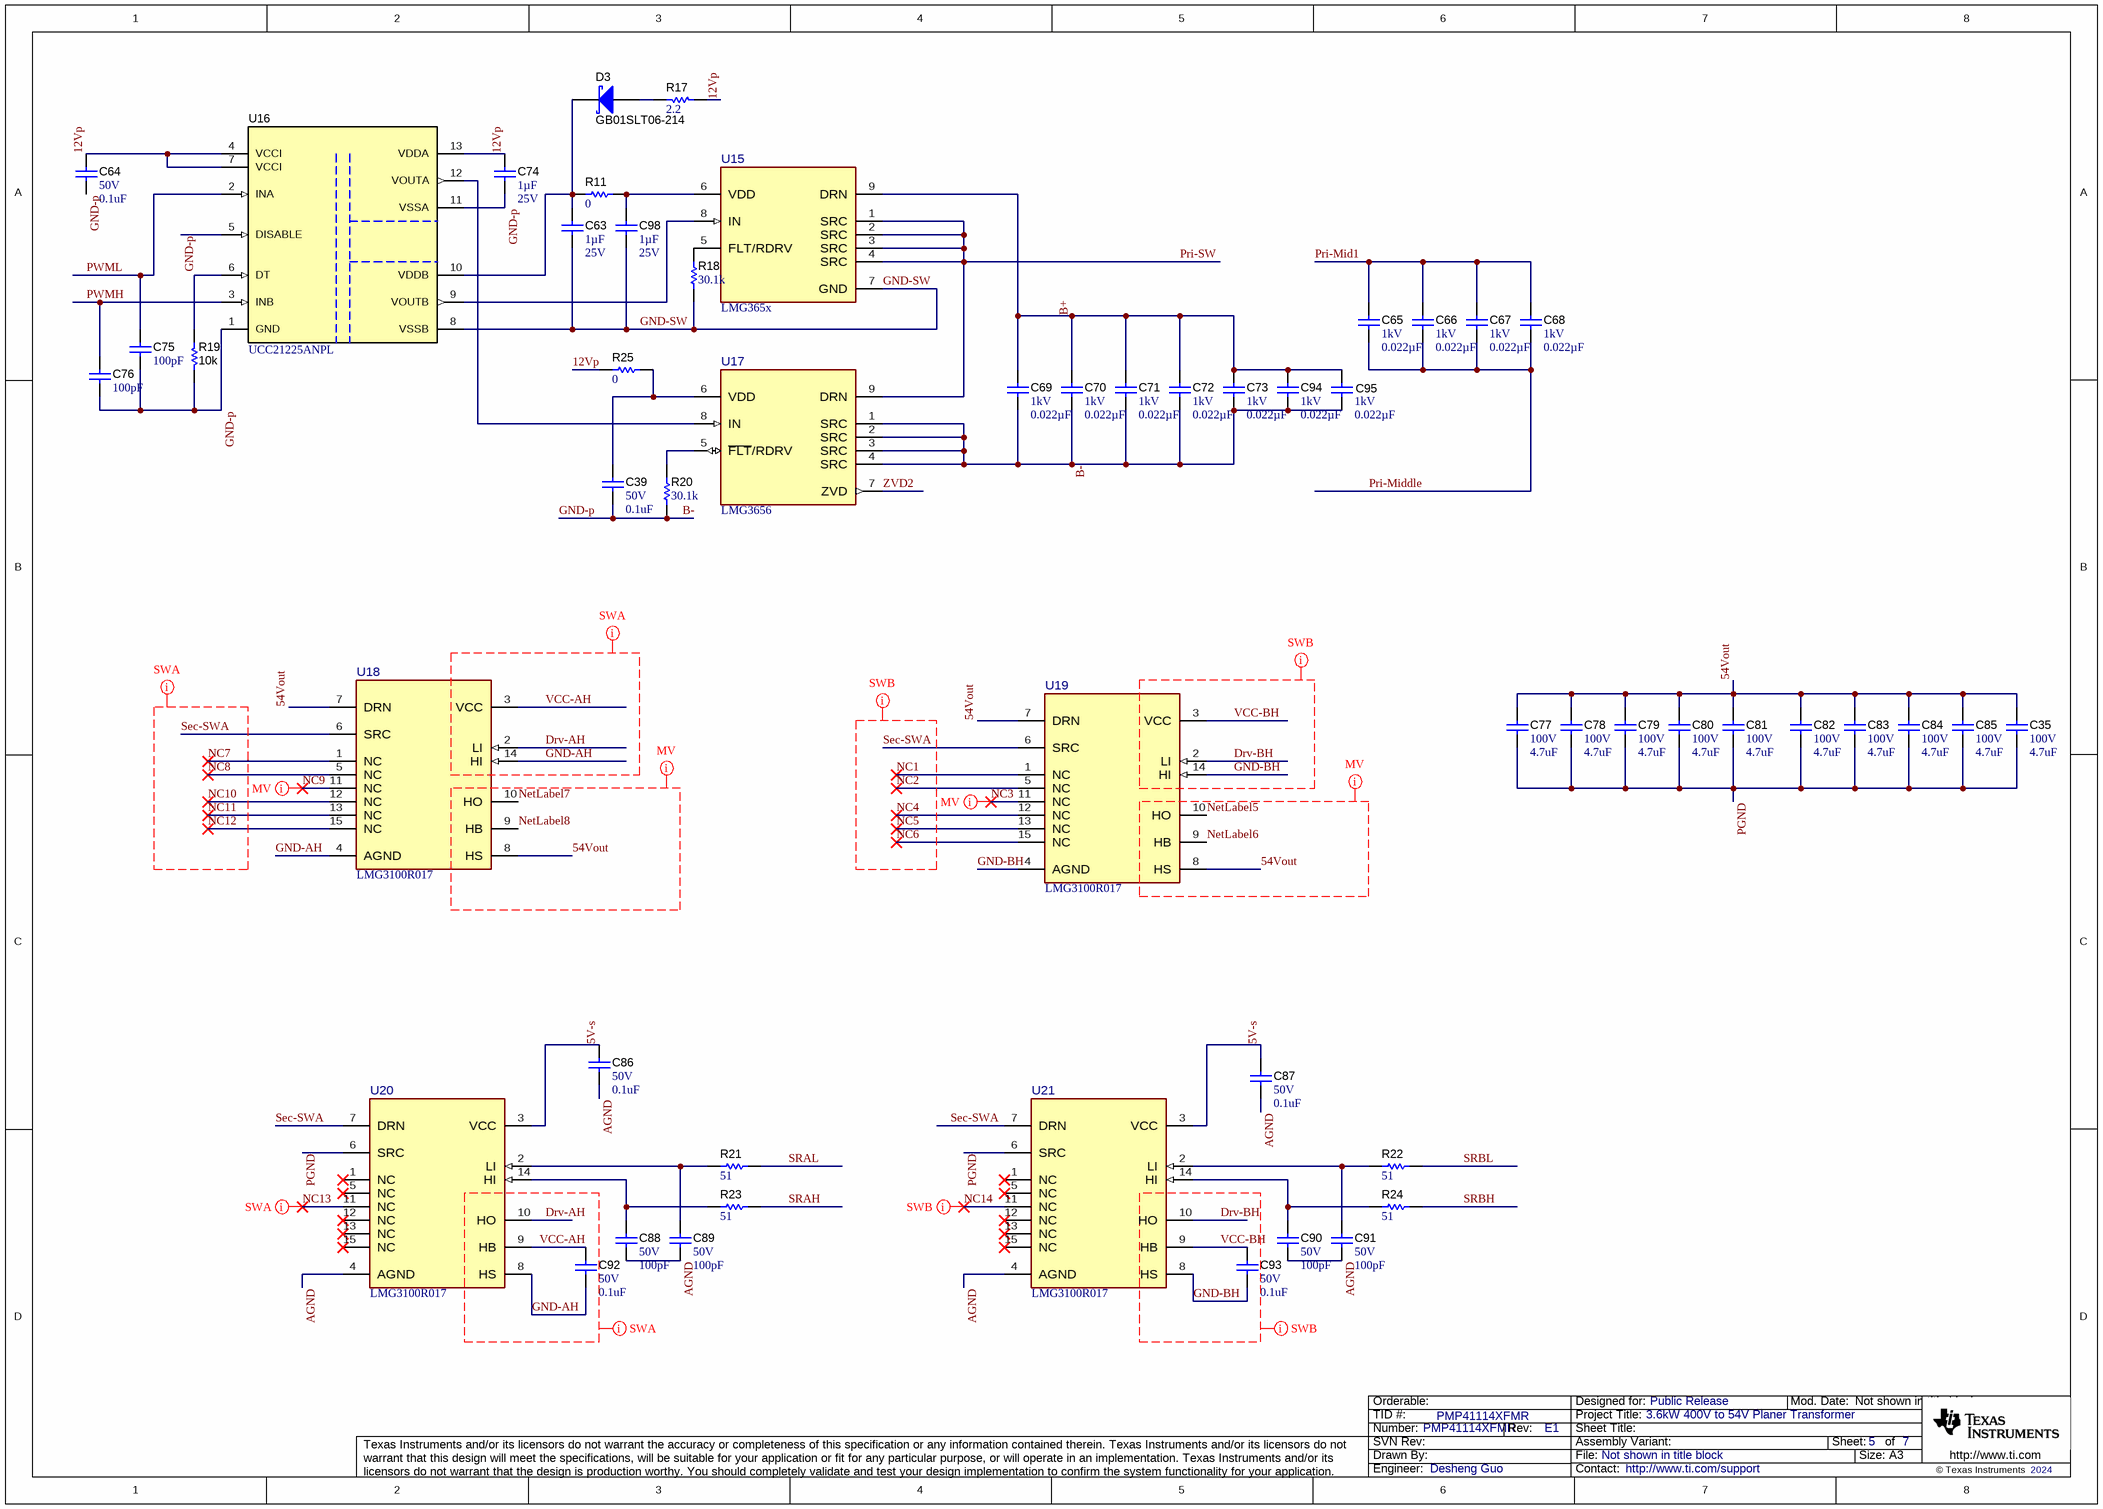
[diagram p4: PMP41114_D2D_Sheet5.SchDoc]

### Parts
C35  VDC_V: 100V  ValueDisplayed: 4.7uF  [1206_180]  (hidden comment: GRM31CZ72A475KE11L)
C39  VDC_V: 50V  ValueDisplayed: 0.1uF  [0402]  (hidden comment: C1005X7R1H104K050BB)
C63  Cap_F: 1µF  VDC_V: 25V  [0603]  (hidden comment: CGJ3E1X7R1E105K080AC)
C64  VDC_V: 50V  ValueDisplayed: 0.1uF  [0402]  (hidden comment: C1005X7R1H104K050BB)
C65  VDC_V: 1kV  ValueDisplayed: 0.022µF  [1206_190]  (hidden comment: C1206C223KDRACTU)
C66  VDC_V: 1kV  ValueDisplayed: 0.022µF  [1206_190]  (hidden comment: C1206C223KDRACTU)
C67  VDC_V: 1kV  ValueDisplayed: 0.022µF  [1206_190]  (hidden comment: C1206C223KDRACTU)
C68  VDC_V: 1kV  ValueDisplayed: 0.022µF  [1206_190]  (hidden comment: C1206C223KDRACTU)
C69  VDC_V: 1kV  ValueDisplayed: 0.022µF  [1206_190]  (hidden comment: C1206C223KDRACTU)
C70  VDC_V: 1kV  ValueDisplayed: 0.022µF  [1206_190]  (hidden comment: C1206C223KDRACTU)
C71  VDC_V: 1kV  ValueDisplayed: 0.022µF  [1206_190]  (hidden comment: C1206C223KDRACTU)
C72  VDC_V: 1kV  ValueDisplayed: 0.022µF  [1206_190]  (hidden comment: C1206C223KDRACTU)
C73  VDC_V: 1kV  ValueDisplayed: 0.022µF  [1206_190]  (hidden comment: C1206C223KDRACTU)
C74  Cap_F: 1µF  VDC_V: 25V  [0603]  (hidden comment: CGJ3E1X7R1E105K080AC)
C75  ValueDisplayed: 100pF  [0402]  (hidden comment: 885012205055)
C76  ValueDisplayed: 100pF  [0402]  (hidden comment: 885012205055)
C77  VDC_V: 100V  ValueDisplayed: 4.7uF  [1206_180]  (hidden comment: GRM31CZ72A475KE11L)
C78  VDC_V: 100V  ValueDisplayed: 4.7uF  [1206_180]  (hidden comment: GRM31CZ72A475KE11L)
C79  VDC_V: 100V  ValueDisplayed: 4.7uF  [1206_180]  (hidden comment: GRM31CZ72A475KE11L)
C80  VDC_V: 100V  ValueDisplayed: 4.7uF  [1206_180]  (hidden comment: GRM31CZ72A475KE11L)
C81  VDC_V: 100V  ValueDisplayed: 4.7uF  [1206_180]  (hidden comment: GRM31CZ72A475KE11L)
C82  VDC_V: 100V  ValueDisplayed: 4.7uF  [1206_180]  (hidden comment: GRM31CZ72A475KE11L)
C83  VDC_V: 100V  ValueDisplayed: 4.7uF  [1206_180]  (hidden comment: GRM31CZ72A475KE11L)
C84  VDC_V: 100V  ValueDisplayed: 4.7uF  [1206_180]  (hidden comment: GRM31CZ72A475KE11L)
C85  VDC_V: 100V  ValueDisplayed: 4.7uF  [1206_180]  (hidden comment: GRM31CZ72A475KE11L)
C86  VDC_V: 50V  ValueDisplayed: 0.1uF  [0402]  (hidden comment: GRM155R71H104ME14D)
C87  VDC_V: 50V  ValueDisplayed: 0.1uF  [0402]  (hidden comment: GRM155R71H104ME14D)
C88  VDC_V: 50V  ValueDisplayed: 100pF  [0402]  (hidden comment: CC0402KRX7R9BB101)
C89  VDC_V: 50V  ValueDisplayed: 100pF  [0402]  (hidden comment: CC0402KRX7R9BB101)
C90  VDC_V: 50V  ValueDisplayed: 100pF  [0402]  (hidden comment: CC0402KRX7R9BB101)
C91  VDC_V: 50V  ValueDisplayed: 100pF  [0402]  (hidden comment: CC0402KRX7R9BB101)
C92  VDC_V: 50V  ValueDisplayed: 0.1uF  [0402]  (hidden comment: C1005X7R1H104K050BE)
C93  VDC_V: 50V  ValueDisplayed: 0.1uF  [0402]  (hidden comment: C1005X7R1H104K050BE)
C94  VDC_V: 1kV  ValueDisplayed: 0.022µF  [1206_190]  (hidden comment: C1206C223KDRACTU)
C95  VDC_V: 1kV  ValueDisplayed: 0.022µF  [1206_190]  (hidden comment: C1206C223KDRACTU)
C98  Cap_F: 1µF  VDC_V: 25V  [0603]  (hidden comment: CGJ3E1X7R1E105K080AC)
D3  GB01SLT06-214  [SMB]
R11  ValueDisplayed: 0  [0402]  (hidden comment: RC0402JR-070RL)
R17  ValueDisplayed: 2.2  [0805_HV]  (hidden comment: RC0805JR-072R2L)
R18  ValueDisplayed: 30.1k  [0402]  (hidden comment: CRCW040230K1FKED)
R19  ValueDisplayed: 10k  [0402]  (hidden comment: CRCW040210K0JNED)
R20  ValueDisplayed: 30.1k  [0402]  (hidden comment: CRCW040230K1FKED)
R21  ValueDisplayed: 51  [0402]  (hidden comment: RC0402JR-0751RL)
R22  ValueDisplayed: 51  [0402]  (hidden comment: RC0402JR-0751RL)
R23  ValueDisplayed: 51  [0402]  (hidden comment: RC0402JR-0751RL)
R24  ValueDisplayed: 51  [0402]  (hidden comment: RC0402JR-0751RL)
R25  ValueDisplayed: 0  [0402]  (hidden comment: RC0402JR-070RL)
U15  LMG365x  [KLA0009A-MFG]
U16  UCC21225ANPL  [NPL0013A]
U17  LMG3656  [KLA0009A-MFG]
U18  LMG3100R017  [VBE0015A-MFG]
U19  LMG3100R017  [VBE0015A-MFG]
U20  LMG3100R017  [VBE0015A-MFG]
U21  LMG3100R017  [VBE0015A-MFG]

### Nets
5V-s: C86.1 C87.1 U20.3(VCC) U21.3(VCC)  [project net 5V-s_5]
12Vp: C64.1 C74.1 R17.1 R25.1 U16.4(VCCI) U16.7(VCCI) U16.13(VDDA)  [project net 12Vp_5]
54Vout: C35.1 C77.1 C78.1 C79.1 C80.1 C81.1 C82.1 C83.1 C84.1 C85.1 U18.7(DRN) U18.8(HS) U19.7(DRN) U19.8(HS)  [project net 54Vout_5]
AGND: C86.2 C87.2 C88.2 C89.2 C90.2 C91.2 U20.4(AGND) U21.4(AGND)  [project net AGND_5]
B+: C69.1 C70.1 C71.1 C72.1 C73.1 C94.1 C95.1 U15.9(DRN)  [project net B+_5]
B-: C39.2 C64.2 C69.2 C70.2 C71.2 C72.2 C73.2 C74.2 C75.2 C76.2 C94.2 C95.2 R19.1 R20.1 U16.1(GND) U16.5(DISABLE) U16.11(VSSA) U17.1(SRC) U17.2(SRC) U17.3(SRC) U17.4(SRC)  [also labelled GND-p]  [project net B-_5]
Drv-AH: U18.2(LI) U20.10(HO)  [project net Drv-AH_5]
Drv-BH: U19.2(LI) U21.10(HO)  [project net Drv-BH_5]
GND-AH: C92.2 U18.4(AGND) U18.14(HI) U20.8(HS)  [project net GND-AH_5]
GND-BH: C93.2 U19.4(AGND) U19.14(HI) U21.8(HS)  [project net GND-BH_5]
GND-SW: C63.2 C98.2 R18.1 U15.7(GND) U16.8(VSSB)  [project net GND-SW_5]
NC1: U19.1(NC)  [project net NC1_5]
NC2: U19.5(NC)  [project net NC2_5]
NC3: U19.11(NC)  [project net NC3_5]
NC4: U19.12(NC)  [project net NC4_5]
NC5: U19.13(NC)  [project net NC5_5]
NC6: U19.15(NC)  [project net NC6_5]
NC7: U18.1(NC)  [project net NC7_5]
NC8: U18.5(NC)  [project net NC8_5]
NC9: U18.11(NC)  [project net NC9_5]
NC10: U18.12(NC)  [project net NC10_5]
NC11: U18.13(NC)  [project net NC11_5]
NC12: U18.15(NC)  [project net NC12_5]
NC13: U20.11(NC)  [project net NC13_5]
NC14: U21.11(NC)  [project net NC14_5]
NetLabel5: U19.10(HO)  [project net NetLabel5_5]
NetLabel6: U19.9(HB)  [project net NetLabel6_5]
NetLabel7: U18.10(HO)  [project net NetLabel7_5]
NetLabel8: U18.9(HB)  [project net NetLabel8_5]
PGND: C35.2 C77.2 C78.2 C79.2 C80.2 C81.2 C82.2 C83.2 C84.2 C85.2 U20.6(SRC) U21.6(SRC)  [project net PGND_5]
Pri-Mid1: C65.1 C66.1 C67.1 C68.1  [project net Pri-Mid1_5]
Pri-Middle: C65.2 C66.2 C67.2 C68.2  [project net Pri-Middle_5]
Pri-SW: U15.1(SRC) U15.2(SRC) U15.3(SRC) U15.4(SRC) U17.9(DRN)  [project net Pri-SW_5]
PWMH: C76.1 U16.3(INB)  [project net PWMH_5]
PWML: C75.1 U16.2(INA)  [project net PWML_5]
Sec-SWA: U18.6(SRC) U19.6(SRC) U20.7(DRN) U21.7(DRN)  [project net Sec-SWA_5]
SRAH: R23.2  [project net SRAH_5]
SRAL: R21.2  [project net SRAL_5]
SRBH: R24.2  [project net SRBH_5]
SRBL: R22.2  [project net SRBL_5]
VCC-AH: C92.1 U18.3(VCC) U20.9(HB)  [project net VCC-AH_5]
VCC-BH: C93.1 U19.3(VCC) U21.9(HB)  [project net VCC-BH_5]
ZVD2: U17.7(ZVD)  [project net ZVD2_5]
NetC39_1: C39.1 R25.2 U17.6(VDD)
NetC63_1: C63.1 D3.1(K) R11.1 U16.10(VDDB)
NetC88_1: C88.1 R23.1 U20.14(HI)
NetC89_1: C89.1 R21.1 U20.2(LI)
NetC90_1: C90.1 R24.1 U21.14(HI)
NetC91_1: C91.1 R22.1 U21.2(LI)
NetC98_1: C98.1 R11.2 U15.6(VDD)
NetD3_2: D3.2(A) R17.2
NetR18_2: R18.2 U15.5(FLT/RDRV)
NetR19_2: R19.2 U16.6(DT)
NetR20_2: R20.2 U17.5(~{FLT}/RDRV)
NetU15_8: U15.8(IN) U16.9(VOUTB)
NetU16_12: U16.12(VOUTA) U17.8(IN)

Not connected (* = marked no-connect by the designer): U20 1(NC)* 5(NC)* 12(NC)* 13(NC)* 15(NC)*; U21 1(NC)* 5(NC)* 12(NC)* 13(NC)* 15(NC)*

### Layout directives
net class MV: 54Vout, NC3_5, NC9_5, NetLabel5, NetLabel6, NetLabel7, NetLabel8
net class SWB: Drv-BH, GND-BH, NC1, NC2, NC4, NC5, NC6, NC14_5, Sec-SWA, VCC-BH
net class SWA: Drv-AH, GND-AH, NC7, NC8, NC10, NC11, NC12, NC13_5, Sec-SWA, VCC-AH

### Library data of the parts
C35 C77-C85 = CMP-0008802-2: as C12 on sheet PMP41114_D2D_Sheet1
C39 C64 = CMP-0006297-2: as C2 on sheet PMP41114_D2D_Sheet1
C63 C74 C98 = CMP-0083856-1: as C1 on sheet PMP41114_D2D_Sheet1
C65-C73 C94 C95 = CMP-0084048-1: as C3 on sheet PMP41114_D2D_Sheet1
C75 C76 = CMP-0006230-2: as C10 on sheet PMP41114_D2D_Sheet1
C86 C87 = CMP-0006675-2: as C21 on sheet PMP41114_D2D_Sheet1
C88-C91 = CMP-0006305-2: as C23 on sheet PMP41114_D2D_Sheet1
C92 C93 = CMP-0064946-2: as C25 on sheet PMP41114_D2D_Sheet1
D3 = CMP-0076998-2: as D1 on sheet PMP41114_D2D_Sheet1
R11 R25 = CMP-0027004-2: as R10 on sheet PMP41114_D2D_Sheet1
R17 = CMP-0020812-2: as R1 on sheet PMP41114_D2D_Sheet1
R18 R20 = CMP-0026284-2: as R2 on sheet PMP41114_D2D_Sheet1
R19 = CMP-0026825-5: as R3 on sheet PMP41114_D2D_Sheet1
R21-R24 = CMP-0027006-2: as R5 on sheet PMP41114_D2D_Sheet1
U15 = CMP-0120607-2: as U1 on sheet PMP41114_D2D_Sheet1
U16 = CMP-0013548-2: as U2 on sheet PMP41114_D2D_Sheet1
U17 = CMP-0122864-1: 650V 25mΩ GaN FET With Integrated Driver and Protection; Manufacturer: Texas Instruments; SizeZ_mm: 2.35mm; AEC Qualified: No; Fall Time: 2.3ns; Max Supply Voltage: 26V; Min Supply Voltage: 9V; Nominal Supply Current: 0.7-5mA; Number Of Drivers: 1; Rise Time: 4.5ns; TJmax_C: +175°C; Turn Off Delay Time: 17ns; Turn On Delay Time: 30ns
U18-U21 = CMP-0043784-1: as U4 on sheet PMP41114_D2D_Sheet1

## Sheet PMP41114_D2D_Sheet4.SchDoc
size 431 x 279 mm; Date: Not shown in title block; ApprovedBy: Not shown in title block; CheckedBy: Not shown in title block; Author: Not shown in title block; CompanyName: Not shown in title block; Engineer: Not shown in title block; Organization: Not shown in title block; Address1: Not shown in title block; Address2: Not shown in title block; Address3: Not shown in title block; Address4: Not shown in title block; DocumentNumber: 2; Revision: Use project parameter SCH_Rev; SheetNumber: 6; SheetTotal: 7; PageSetup: Record=PageOptions¦CenterHorizontal=True¦CenterVertical=True¦PrintScale=1.00¦XCorrection=1.00¦YCorrection=1.00¦PrintKind=0¦BorderSize=5000000¦LeftOffset=0¦BottomOffset=0¦Orientation=2¦PaperLength=1000¦PaperWidth=1000¦Scale=100¦PaperSource=15¦PrintQuality=600¦MediaType=1¦DitherType=10¦PaperKind=Letter¦PrintScaleMode=1
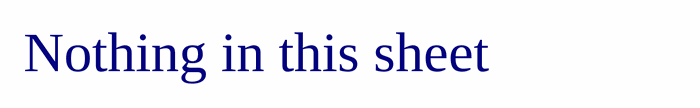
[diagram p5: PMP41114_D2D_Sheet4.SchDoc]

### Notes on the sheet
- Nothing in this sheet

## Sheet PMP41114_D2D_Hardware.SchDoc
size 431 x 279 mm; Date: Not shown in title block; ApprovedBy: Not shown in title block; CheckedBy: Not shown in title block; Author: Not shown in title block; CompanyName: Not shown in title block; Engineer: Not shown in title block; Organization: Not shown in title block; Address1: Not shown in title block; Address2: Not shown in title block; Address3: Not shown in title block; Address4: Not shown in title block; DocumentNumber: 3; Revision: Use project parameter SCH_Rev; SheetNumber: 3; SheetTotal: 3; PageSetup: Record=PageOptions¦CenterHorizontal=True¦CenterVertical=True¦PrintScale=1.00¦XCorrection=1.00¦YCorrection=1.00¦PrintKind=0¦BorderSize=5000000¦LeftOffset=0¦BottomOffset=0¦Orientation=2¦PaperLength=1000¦PaperWidth=1000¦Scale=100¦PaperSource=15¦PrintQuality=600¦MediaType=1¦DitherType=10¦PaperKind=Letter¦PrintScaleMode=1
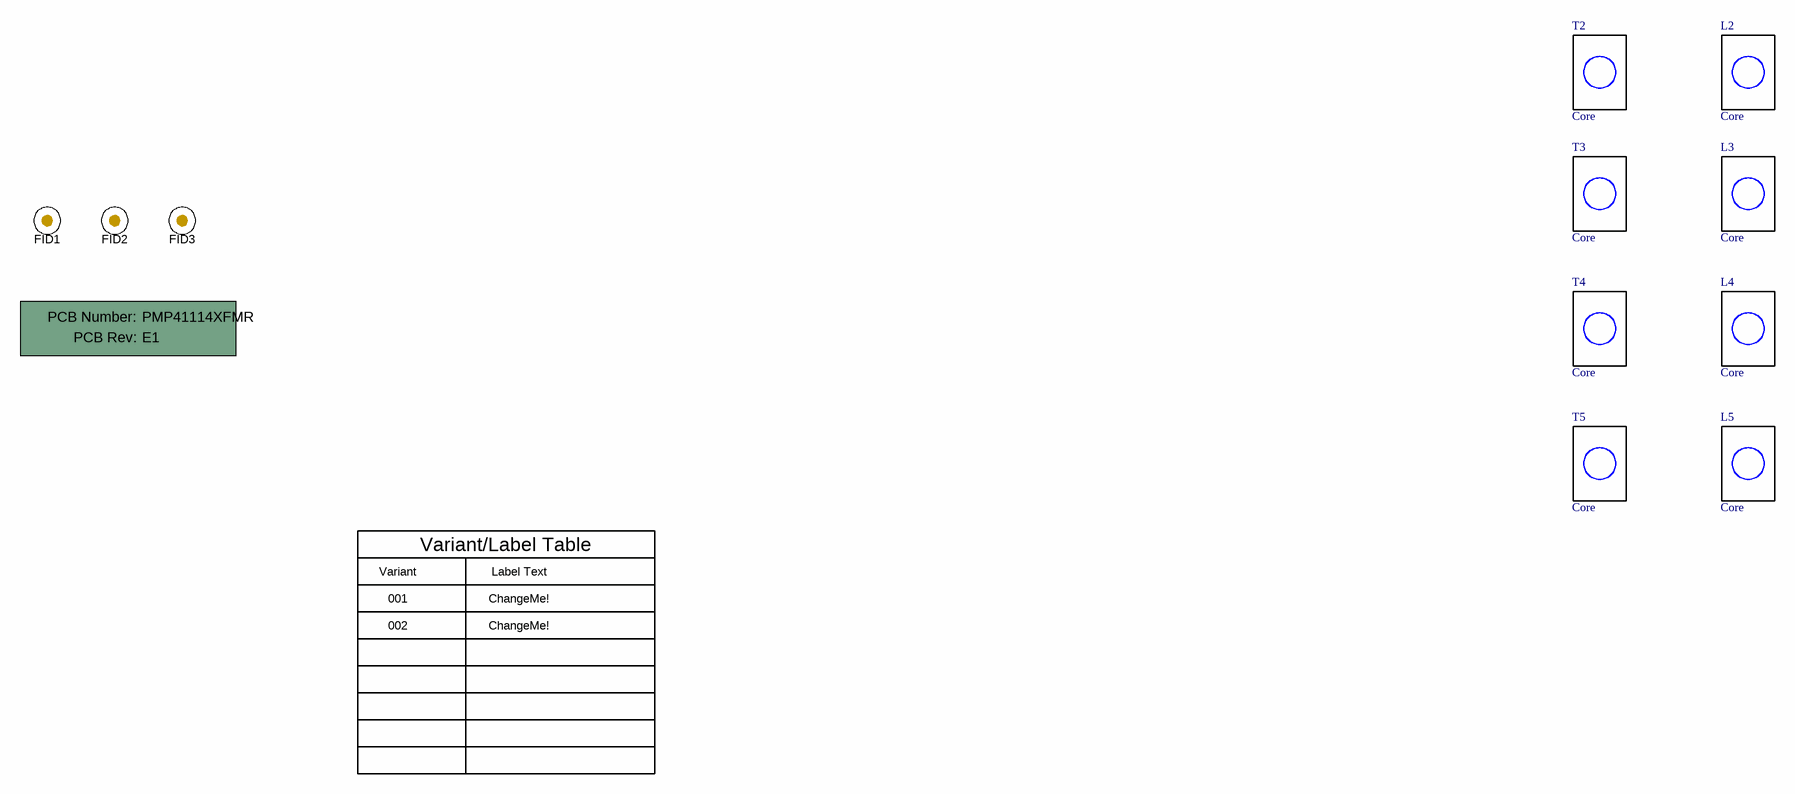
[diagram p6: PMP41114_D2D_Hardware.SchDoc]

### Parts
!PCB  Printed Circuit Board  (value not drawn)  (mechanical)
FID1  Fiducial  [Fiducial10-20]  (value not drawn)
FID2  Fiducial  [Fiducial10-20]  (value not drawn)
FID3  Fiducial  [Fiducial10-20]  (value not drawn)
L2  Core  [ER25/10/11]  (no BOM)
L3  Core  [ER25/10/11]  (no BOM)
L4  Core  [ER25/10/11]  (no BOM)
L5  Core  [ER25/10/11]  (no BOM)
T2  Core  [PQ32]  (no BOM)
T3  Core  [PQ32]  (no BOM)
T4  Core  [PQ32]  (no BOM)
T5  Core  [PQ32]  (no BOM)

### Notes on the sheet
- Variant
- Variant/Label Table
- Label Text
- 001
- 002
- ChangeMe!

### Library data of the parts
!PCB = CMP-0003618-2: Manufacturer: Any; PartNumber: PMP41114XFMR
FID1-FID3 = CMP-0077181-1: Fiducial mark.  There is nothing to buy or mount.
L2-L5 T2-T5 = CorePlace

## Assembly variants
001: not fitted FID1 FID2 FID3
